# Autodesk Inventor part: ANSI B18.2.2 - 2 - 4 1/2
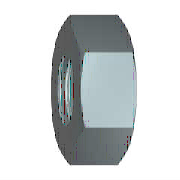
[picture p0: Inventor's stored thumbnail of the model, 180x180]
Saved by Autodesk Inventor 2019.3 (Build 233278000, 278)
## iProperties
Created: 2018-01
Part Number: ANSI B18.2.2 - 2 - 4 1/2
Material: Steel, Mild
Description: Hex Nuts (Inch Series) Heavy Hex Nut
Document SubType Name: Modeling
Standard: ANSI B18.2.2
Designer: u1426
Standard Revision: 2010
Standards Organization: ANSI
Language: en-US
Size Designation: 2 - 4 1/2
Categories: <MemberInstance><Categories><Category DisplayName="Fasteners" InternalName="e4da775c-781d-43d5-af7c-5136215cf5a6" Mnemonic="FSTN"><Category DisplayName="Nuts" I
Density: 7.85 g/cm^3
Appearance: Semi-Polished
IsCustomPart: 0
Author: u1426
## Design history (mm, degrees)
sketch "Sketch1"
  geometry: L1 (-45.827, 0)-(-22.914, 39.688); L2 (-22.914, 39.688)-(22.914, 39.688); L3 (22.914, 39.688)-(45.827, 0); L4 (45.827, 0)-(22.914, -39.687); L5 (22.914, -39.687)-(-22.914, -39.688); L6 (-22.914, -39.688)-(-45.827, 0); 2 further points
  constraints: 12 end point, 1 coincident, 1 horizontal, 11 other
  dimensions: "d0" = 91.65436 distance of L3.end L1.start (= 1.1547 x SW)
extrude "Body" new body sketch "Sketch1" distance "d1" = 50.0126 (= KOH); taper "d2" = 0 deg
sketch "Sketch2"
  geometry: L1 (0, 22.914)-(0, 45.827) reference; L2 (0, 45.827)-(50.013, 45.827) reference; L3 (50.013, 22.914)-(50.013, 45.827) reference; L4 (-10.003, 0)-(60.015, 0) reference; L5 (2.863, 45.827)-(0, 39.688); L6 (47.15, 45.827)-(50.013, 39.688)
  constraints: 4 end point, 4 point on line
  dimensions: "d3" = 25 deg angle of L1 L5 (= ANG1); "d4" = 25 deg angle of L3 L6 (= ANG2); "d5" = 79.375 diameter of L5.end L4 (= SW0); "d6" = 79.375 diameter of L6.end L4 (= SW01)
revolve "Chamfer1" sketch "Sketch2" stored, may be unused: angle "d7" = 90 deg
sketch "Sketch3"
  geometry: A1 r 39.687 centre (0, 0) between (-19.844, -34.37) and (19.844, -34.37) reference; 1 further point
  constraints: 1 coincident
hole "Thread" sketch "Sketch3" at (0, 0) diameter "d25" = 44.6786; stored, may be unused: countersink angle "d29" = 82 deg, drill point angle "d31" = 118 deg; dims "d26" = 6, "d27" = 4, "d28" = 2, "d30" = 8
workaxis "Work Axis1"
workplane "Work Plane1"
body "Solid1"
chamfer "Chamfer2" distance "d8" = 3.05515 (= -0.5 x GD1 + 0.5 x NND); stored, may be unused: angle "d9" = 30 deg, second distance "d40" = 3.05515 (= -0.5 x GD1 + 0.5 x NND)
chamfer "Chamfer3" distance "d10" = 3.05515 (= -0.5 x GD1 + 0.5 x NND); stored, may be unused: angle "d11" = 30 deg, second distance "d41" = 3.05515 (= -0.5 x GD1 + 0.5 x NND)
other parameters: "ANG1" = 25 deg [user parameter; used in 1 equation term], "ANG2" = 25 deg [user parameter; used in 1 equation term], "NND" = 50.8 [user parameter; used in 4 equation terms], "KOH" = 50.0126 [user parameter; used in 1 equation term], "SW" = 79.375 [user parameter; used in 4 equation terms], "SW0" = 79.375 (= SW) [user parameter; used in 1 equation term], "SW01" = 79.375 (= SW) [user parameter; used in 1 equation term], "GD1" = 44.68971 (computed from THREADDIA, PTC, TOA) [user parameter; used in 4 equation terms], "d13" = 0, "d14" = 0, "d39" = 0, "d42" = 0, "TPU" = 45 [user parameter; used in 1 equation term], "THREADDIA" = 50.8 [user parameter; used in 1 equation term], "TOA" = 30 deg [user parameter; used in 1 equation term], "PTC" = 5.64444 (computed from TPU) [user parameter; used in 1 equation term], "E0" = 91.67812 (= 1.155 x SW) [user parameter]
